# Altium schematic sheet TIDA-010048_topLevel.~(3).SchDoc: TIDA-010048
size 431 x 279 mm; Date: Not shown in title block; ApprovedBy: Not shown in title block; CheckedBy: Not shown in title block; Author: Not shown in title block; CompanyName: Not shown in title block; Engineer: Not shown in title block; Organization: Not shown in title block; Address1: Not shown in title block; Address2: Not shown in title block; Address3: Not shown in title block; Address4: Not shown in title block; DocumentNumber: 1; Revision: Use project parameter SCH_Rev; SheetNumber: 2; SheetTotal: 3; PageSetup: Record=PageOptions¦CenterHorizontal=True¦CenterVertical=True¦PrintScale=1.00¦XCorrection=1.00¦YCorrection=1.00¦PrintKind=0¦BorderSize=5000000¦LeftOffset=0¦BottomOffset=0¦Orientation=2¦PaperLength=1000¦PaperWidth=1000¦Scale=100¦PaperSource=15¦PrintQuality=600¦MediaType=1¦DitherType=10¦PaperKind=Letter¦PrintScaleMode=1
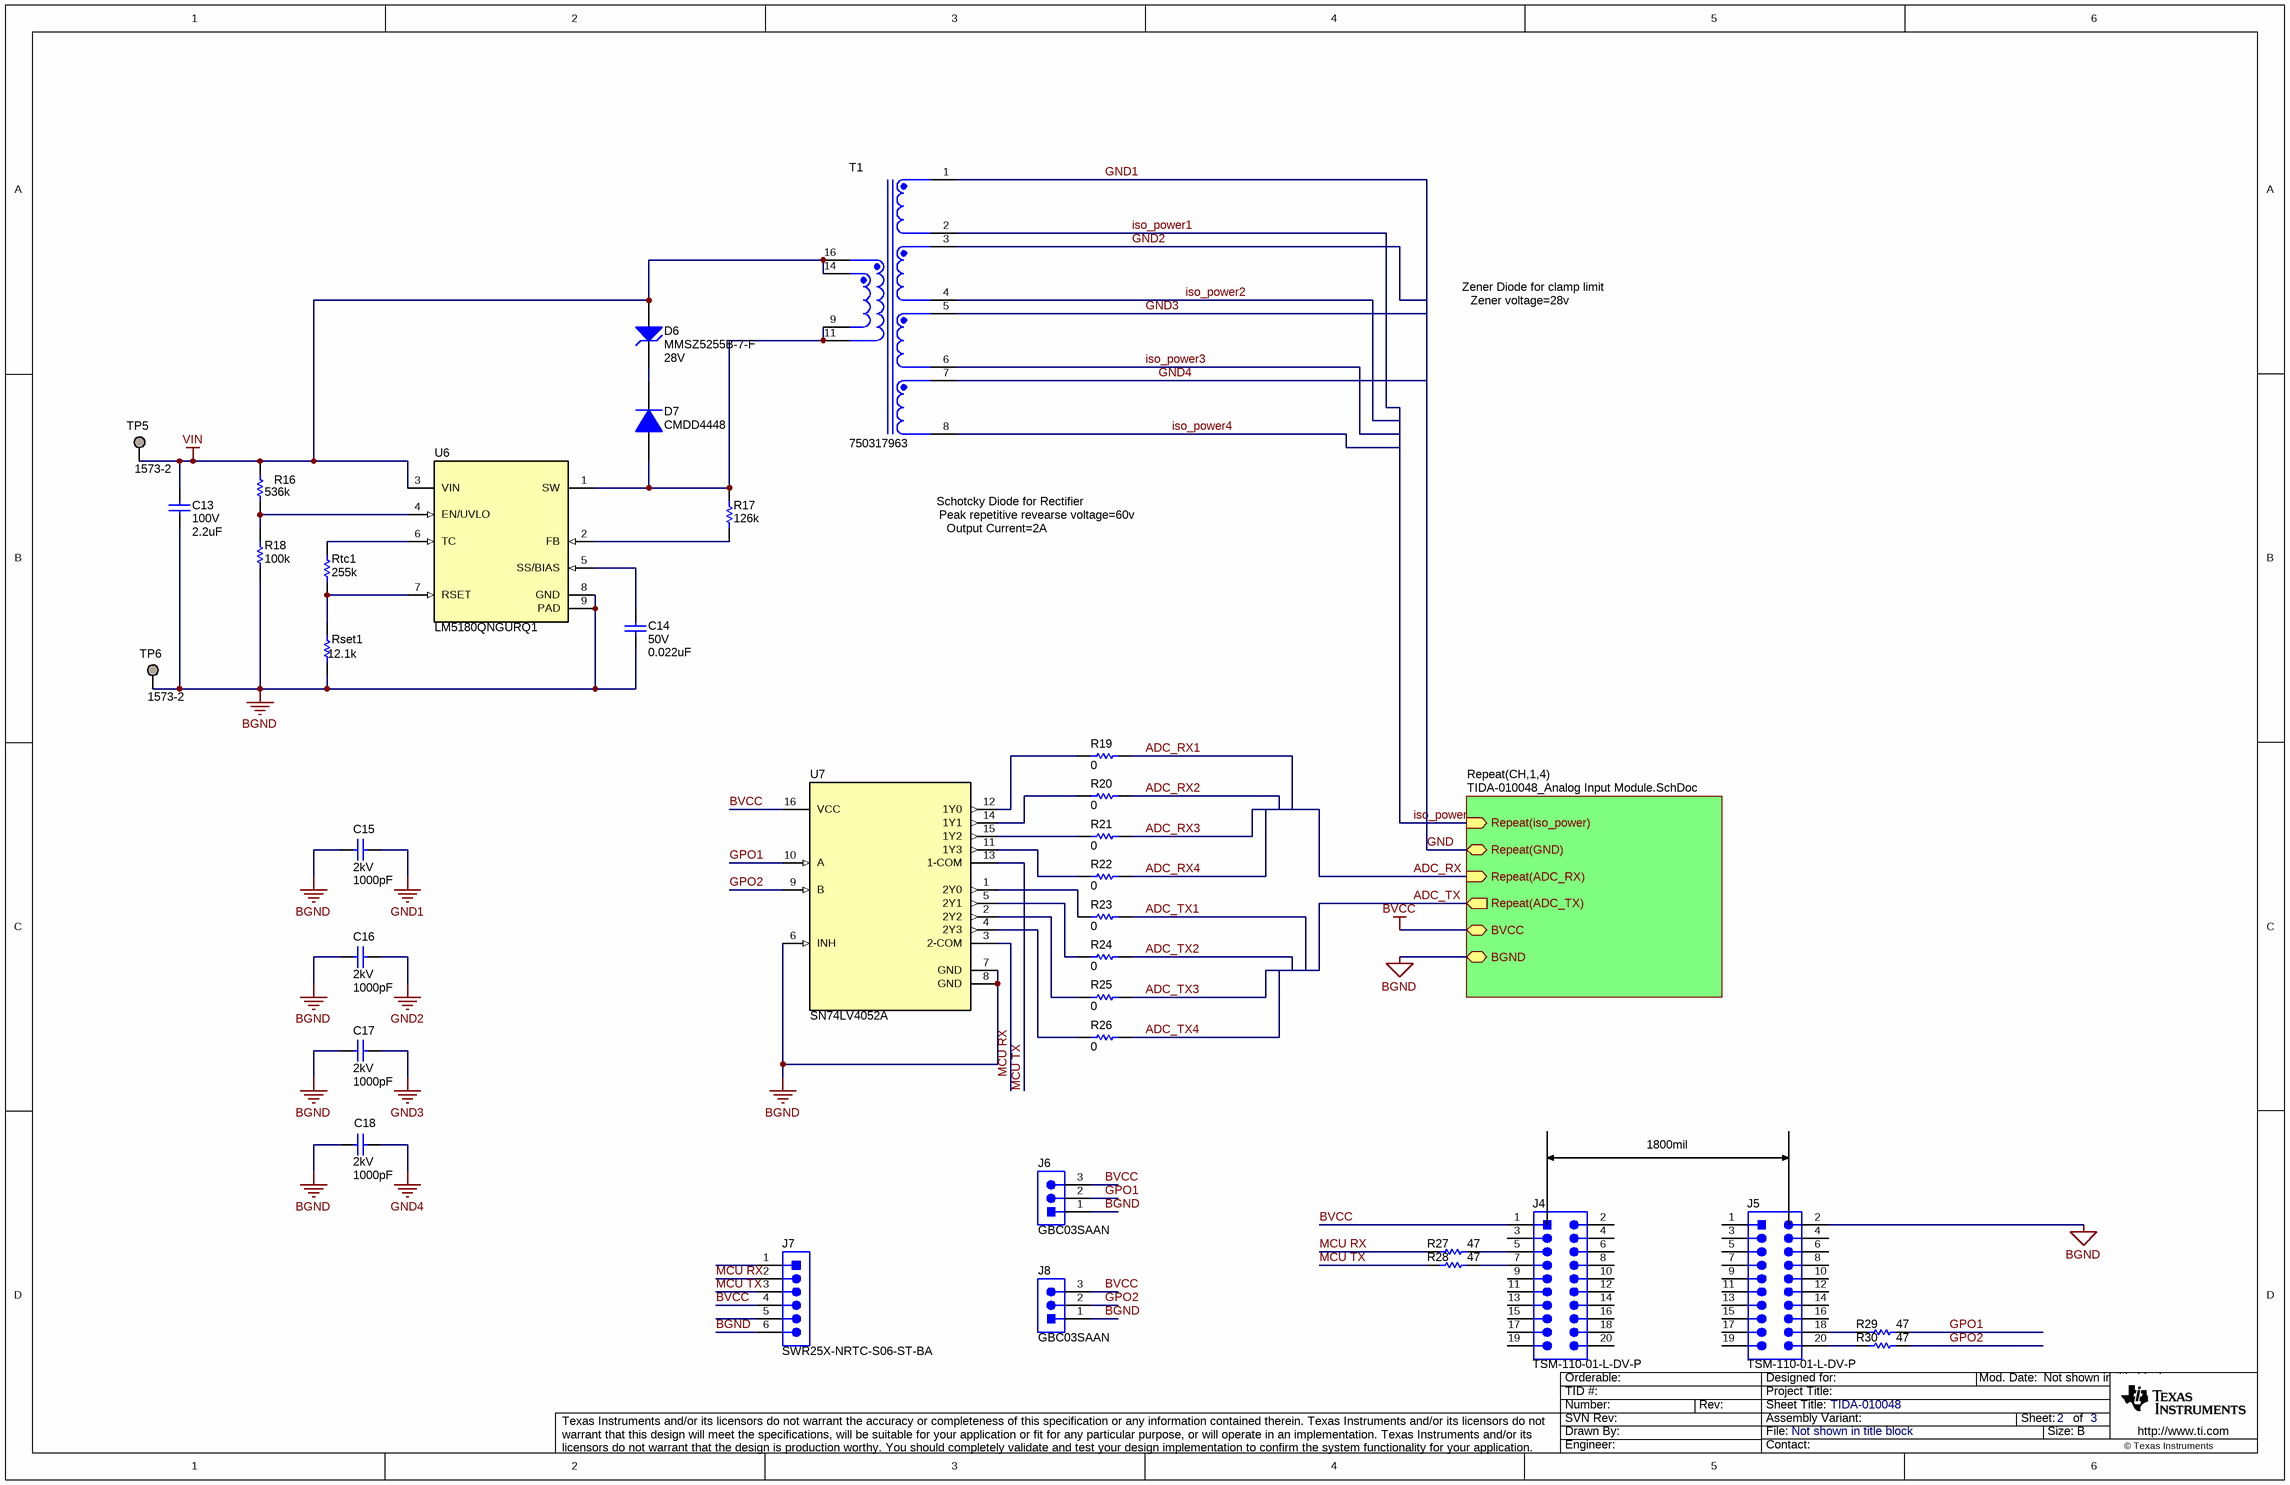
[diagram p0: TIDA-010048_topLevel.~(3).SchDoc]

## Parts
C13  VDC_V: 100V  ValueDisplayed: 2.2uF  [1210_210]  (hidden comment: C1210C225K1RACTU)
C14  VDC_V: 50V  ValueDisplayed: 0.022uF  [0603]  (hidden comment: C0603X223K5RACTU)
C15  VDC_V: 2kV  ValueDisplayed: 1000pF  [1812]  (hidden comment: GR443QR73D102KW01L)
C16  VDC_V: 2kV  ValueDisplayed: 1000pF  [1812]  (hidden comment: GR443QR73D102KW01L)
C17  VDC_V: 2kV  ValueDisplayed: 1000pF  [1812]  (hidden comment: GR443QR73D102KW01L)
C18  VDC_V: 2kV  ValueDisplayed: 1000pF  [1812]  (hidden comment: GR443QR73D102KW01L)
D6  MMSZ5255B-7-F  value 28V  [SOD-123]
D7  CMDD4448  [SOD-323]
J4  TSM-110-01-L-DV-P  [CONN_TSM-110-01-T-DV-P]
J5  TSM-110-01-L-DV-P  [CONN_TSM-110-01-T-DV-P]
J6  GBC03SAAN  [Sullins_Gxx03SAAN]
J7  SWR25X-NRTC-S06-ST-BA  [Sullins_SWR25X-NRTC-S06-ST-BA]
J8  GBC03SAAN  [Sullins_Gxx03SAAN]
R16  ValueDisplayed: 536k  [0603]  (hidden comment: RC0603FR-07536KL)
R17  ValueDisplayed: 126k  [0603]  (hidden comment: RT0603DRE07126KL)
R18  ValueDisplayed: 100k  [0603]  (hidden comment: RC0603FR-07100KL)
R19  ValueDisplayed: 0  [0603]  (hidden comment: CRCW06030000Z0EA)
R20  ValueDisplayed: 0  [0603]  (hidden comment: CRCW06030000Z0EA)
R21  ValueDisplayed: 0  [0603]  (hidden comment: CRCW06030000Z0EA)
R22  ValueDisplayed: 0  [0603]  (hidden comment: CRCW06030000Z0EA)
R23  ValueDisplayed: 0  [0603]  (hidden comment: CRCW06030000Z0EA)
R24  ValueDisplayed: 0  [0603]  (hidden comment: CRCW06030000Z0EA)
R25  ValueDisplayed: 0  [0603]  (hidden comment: CRCW06030000Z0EA)
R26  ValueDisplayed: 0  [0603]  (hidden comment: CRCW06030000Z0EA)
R27  ValueDisplayed: 47  [0603]  (hidden comment: CRCW060347R0JNEA)
R28  ValueDisplayed: 47  [0603]  (hidden comment: CRCW060347R0JNEA)
R29  ValueDisplayed: 47  [0603]  (hidden comment: CRCW060347R0JNEA)
R30  ValueDisplayed: 47  [0603]  (hidden comment: CRCW060347R0JNEA)
Rset1  ValueDisplayed: 12.1k  [0603]  (hidden comment: RC0603FR-0712K1L)
Rtc1  ValueDisplayed: 255k  [0603]  (hidden comment: RC0603FR-07255KL)
T1  750317963  [Wurth_750317963]
TP5  1573-2  [Keystone1573-2]
TP6  1573-2  [Keystone1573-2]
U6  LM5180QNGURQ1  [NGU0008C]
U7  SN74LV4052A  [PW0016A_L]

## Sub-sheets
Repeat(CH,1,4) = TIDA-010048_Analog Input Module.SchDoc: Repeat(iso_power) (in), Repeat(ADC_TX) (out), Repeat(ADC_RX) (in), BVCC (bidir), Repeat(GND), BGND (bidir)

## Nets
BGND: C13.2 C14.2 C15.2 C16.2 C17.2 C18.2 J5.2 J6.1 J7.6 J8.1 R18.1 Rset1.1 TP6.1 U6.8(GND) U6.9(PAD) U7.6(INH) U7.7(GND) U7.8(GND) ; sheet Repeat(CH,1,4)/BGND
BVCC: J4.1 J6.3 J7.4 J8.3 U7.16(VCC) ; sheet Repeat(CH,1,4)/BVCC
GND1: C15.1 T1.1
GND2: C16.1 T1.3
GND3: C17.1 T1.5
GND4: C18.1 T1.7
VIN: C13.1 D6.2(A) R16.2 T1.14 T1.16 TP5.1 U6.3(VIN)
ADC_RX1: R19.2
ADC_RX2: R20.2
ADC_RX3: R21.2
ADC_RX4: R22.2
ADC_TX1: R23.2
ADC_TX2: R24.2
ADC_TX3: R25.2
ADC_TX4: R26.2
GPO1: J6.2 R29.2 U7.10(A)
GPO2: J8.2 R30.2 U7.9(B)
iso_power1: T1.2
iso_power2: T1.4
iso_power3: T1.6
iso_power4: T1.8
MCU RX: J7.2 R27.1 U7.3(2-COM)
MCU TX: J7.3 R28.1 U7.13(1-COM)
NetC14_1: C14.1 U6.5(SS/BIAS)
NetD6_1: D6.1(K) D7.1(K)
NetD7_2: D7.2(A) R17.2 T1.9 T1.11 U6.1(SW)
NetJ4_5: J4.5 R27.2
NetJ4_7: J4.7 R28.2
NetJ5_18: J5.18 R29.1
NetJ5_20: J5.20 R30.1
NetR16_1: R16.1 R18.2 U6.4(EN/UVLO)
NetR17_1: R17.1 U6.2(FB)
NetR19_1: R19.1 U7.12(1Y0)
NetR20_1: R20.1 U7.14(1Y1)
NetR21_1: R21.1 U7.15(1Y2)
NetR22_1: R22.1 U7.11(1Y3)
NetR23_1: R23.1 U7.1(2Y0)
NetR24_1: R24.1 U7.5(2Y1)
NetR25_1: R25.1 U7.2(2Y2)
NetR26_1: R26.1 U7.4(2Y3)
NetRset1_2: Rset1.2 Rtc1.1 U6.7(RSET)
NetRtc1_2: Rtc1.2 U6.6(TC)

Not connected (* = marked no-connect by the designer): J4 2 3 4 6 8 9 10 11 12 13 14 15 16 17 18 19 20; J5 1 3 4 5 6 7 8 9 10 11 12 13 14 15 16 17 19; J7 1 5

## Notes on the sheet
- Zener voltage=28v
- Zener Diode for clamp limit
- Schotcky Diode for Rectifier
- Output Current=2A
- Peak repetitive revearse voltage=60v
- 1800mil

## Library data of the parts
C13 = CMP-0009084-1: CAP, CERM, 2.2 uF, 100 V, +/- 10%, X7R, 1210; Manufacturer: Kemet; TaMin_C: -55°C; Polarized: N; SizeAreaWB_mm2: 14.7; Value1: Unknown; U/M: EA; Value: 2.2uF; TaMax_C: 125°C; SizeZ_mm: 2.1; SizeX_mm: 3.2; SizeY_mm: 2.5; Cap_Case: 1210; SizeArea_mm2: 8; CompType: Capacitor; Cap_F: 2.2µF; AEC Category: Q200
C14 = CMP-0006984-4: CAP, CERM, 0.022 uF, 50 V, +/- 10%, X7R, 0603; Manufacturer: Kemet; TaMin_C: -55°C; Polarized: N; SizeAreaWB_mm2: 4.68; Value1: Unknown; U/M: EA; TaMax_C: 125°C; SizeZ_mm: 1; SizeX_mm: 1.6; SizeY_mm: 0.8; SizeArea_mm2: 1.28; CompType: Capacitor; Cap_F: 22nF; AEC Category: Q200
C15-C18 = CMP-0009438-2: CAP, CERM, 1000 pF, 2000 V, +/- 10%, X7R, 1812; Manufacturer: MuRata; TaMin_C: -55°C; Polarized: N; SizeAreaWB_mm2: 23.1; Value1: Unknown; U/M: EA; Value: 1000pF; TaMax_C: 125°C; SizeZ_mm: 1.35; SizeX_mm: 4.5; SizeY_mm: 3.2; Value2: 2000V; SizeArea_mm2: 14.4; Cap_F: 1nF; AEC Category: Q200
D6 = CMP-0005760-4: Diode, Zener, 28 V, 500 mW, SOD-123; Manufacturer: Diodes Inc.; SizeArea_mm2: 6.545; Value1: 0.5W; SizeZ_mm: 1.35; AEC Category: Q101; SizeY_mm: 1.7; Power_W: 500mW; SizeAreaWB_mm2: 13.095; RJA_CperW: 350; SizeX_mm: 3.85
D7 = CMP-0029019-2: Diode, Ultrafast, 75 V, 0.25 A, SOD-323; Manufacturer: Central Semiconductor; Io_A: 2.5dA; SizeX_mm: 2.7; Vf_V: 1.2V; TJmax_C: 175°C; SizeAreaWB_mm2: 8.695; SizeArea_mm2: 3.645; Vr_V: 75V; Green_Lifecycle: Not Set; Green_REACh: Incomplete; AEC Category: Q101; Value: 75V; Value1: 0.25A; SizeZ_mm: 1; SizeY_mm: 1.35
J4 J5 = CMP-0075600-1: Header, 2.54mm, 10x2, Gold, SMT; Manufacturer: Samtec; Pitch_mm: 2.54; Gender: Male; Cert_CSA: Y; Green_REACh: Passed; Current_A: 5.4A; Voltage_V: 475V; CT: False; Shrouded: N; Green_Lifecycle: Active; Row_Count: 2; CNHeader: True
J6 J8 = CMP-0054577-1: Header, 2.54 mm, 3x1, Gold, TH; Manufacturer: Sullins Connector Solutions; CT: FALSE; CNHeader: TRUE
J7 = CMP-0054740-1: Header, 2.54mm, 6x1, Tin, TH; Manufacturer: Sullins Connector Solutions; CNHeader: FALSE; Current_A: 3A; Gender: Male; Voltage_V: 250V; Row_Count: 1; Pitch_mm: 2.54; Cert_UL: Y
R16 = CMP-0023174-4: RES, 536 k, 1%, 0.1 W, 0603; Manufacturer: Yageo; Power_W: 100mW; TempCo: 100 ppm/C; Value: 536k; EIA_Code: E96; SizeX_mm: 1.6; SizeY_mm: 0.8; SizeZ_mm: 1; Value2: 0.1W; SizeArea_mm2: 1.28; CompType: Resistor; AEC Qualified: N; VDC_V: 75V; AEC Category: Q200; SizeAreaWB_mm2: 4.68
R17 = CMP-0024631-2: RES, 126 k, 0.5%, 0.1 W, 0603; Manufacturer: Yageo America; Power_W: 100mW; TempCo: 50 ppm/C; U/M: EA; Value: 126k; EIA_Code: E192; SizeX_mm: 1.6; SizeY_mm: 0.8; SizeZ_mm: 1; Value2: 0.1W; SizeArea_mm2: 1.28; CompType: Resistor; VDC_V: 75V; AEC Category: Q200
R18 = CMP-0022735-5: RES, 100 k, 1%, 0.1 W, 0603; Manufacturer: Yageo; Power_W: 100mW; TempCo: 100 ppm/C; Value: 100k; EIA_Code: E96; SizeX_mm: 1.6; SizeY_mm: 0.8; SizeZ_mm: 1; Value2: 0.1W; SizeArea_mm2: 1.28; CompType: Resistor; AEC Qualified: N; VDC_V: 75V; AEC Category: Q200; SizeAreaWB_mm2: 4.68
R19-R26 = CMP-0025697-4: RES, 0, 5%, 0.1 W, AEC-Q200 Grade 0, 0603; Manufacturer: Vishay-Dale; Power_W: 100mW; TempCo: 200 ppm/C; Value_Code: 0000; Value: 0; EIA_Code: E24; SizeX_mm: 1.6; SizeY_mm: 0.8; SizeZ_mm: 1; Value2: 0.1W; SizeArea_mm2: 1.28; AEC Qualified: Y; VDC_V: 75V; AEC Category: Q200
R27-R30 = CMP-0025815-2: RES, 47, 5%, 0.1 W, 0603; Manufacturer: Vishay-Dale; Power_W: 100mW; TempCo: 200 ppm/C; Value_Code: 47R0; U/M: EA; Value: 47; EIA_Code: E24; SizeX_mm: 1.6; SizeY_mm: 0.8; SizeZ_mm: 1; Value2: 0.1W; SizeArea_mm2: 1.28; VDC_V: 75V; AEC Category: Q200
Rset1 = CMP-0022776-5: RES, 12.1 k, 1%, 0.1 W, 0603; Manufacturer: Yageo; Power_W: 100mW; TempCo: 100 ppm/C; Value_Code: 12k1; Value: 12.1k; EIA_Code: E96; SizeX_mm: 1.6; SizeY_mm: 0.8; SizeZ_mm: 1; Value2: 0.1W; SizeArea_mm2: 1.28; CompType: Resistor; AEC Qualified: N; VDC_V: 75V; AEC Category: Q200; SizeAreaWB_mm2: 4.68
Rtc1 = CMP-0022949-4: RES, 255 k, 1%, 0.1 W, 0603; Manufacturer: Yageo; Power_W: 100mW; TempCo: 100 ppm/C; Value: 255k; EIA_Code: E96; SizeX_mm: 1.6; SizeY_mm: 0.8; SizeZ_mm: 1; Value2: 0.1W; SizeArea_mm2: 1.28; CompType: Resistor; AEC Qualified: N; VDC_V: 75V; AEC Category: Q200; SizeAreaWB_mm2: 4.68
T1 = CMP-0084723-1: Transformer, 22 uH, TH; Manufacturer: Wurth Elektronik; Rsec2_ohm: 4.25d; DCR_ohm: 0.036; Value: 22uH; Ind_H: 22µH; LeakageInd_H: 75nH; SizeArea_mm2: 213.0425; SizeAreaWB_mm2: 275.4825; SizeY_mm: 15.25; Ns1toNp: 2; SizeX_mm: 13.97; Rsec3_ohm: 5.15d; AEC Qualified: N; AEC Category: Q200; Lp: 22; SizeZ_mm: 12.7
TP5 TP6 = CMP-0055119-1: Terminal, Turret, TH, Double; Manufacturer: Keystone; CT: FALSE; Green_REACh: Passed; CompType: Turret Terminal; Green_Lifecycle: Active
U6 = CMP-0078633-2: 70-V PSR Flyback Converter With 100-V, 1.2-A Power Switch and Ultra-Low IQ, NGU0008C (WSON-8); Alternate PartNumber: LM5180QNGUTQ1; Alternate Manufacturer: Texas Instruments; SizeAreaWB_mm2: 25; SizeZ_mm: 0.8; SizeX_mm: 4; SizeArea_mm2: 16; CompType: IC; AEC Qualified: Y; AEC Category: Q200
U7 = CMP-0066257-1: Automotive Catalog Dual 4-Channel Analog Multiplexer/Demultiplexer, PW0016A (TSSOP-16); Alternate Manufacturer: Texas Instruments; SizeAreaWB_mm2: 58.8; U/M: EA; SizeZ_mm: 1.2; SizeX_mm: 6.4; SizeY_mm: 5.0; SizeArea_mm2: 32.0; CompType: IC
